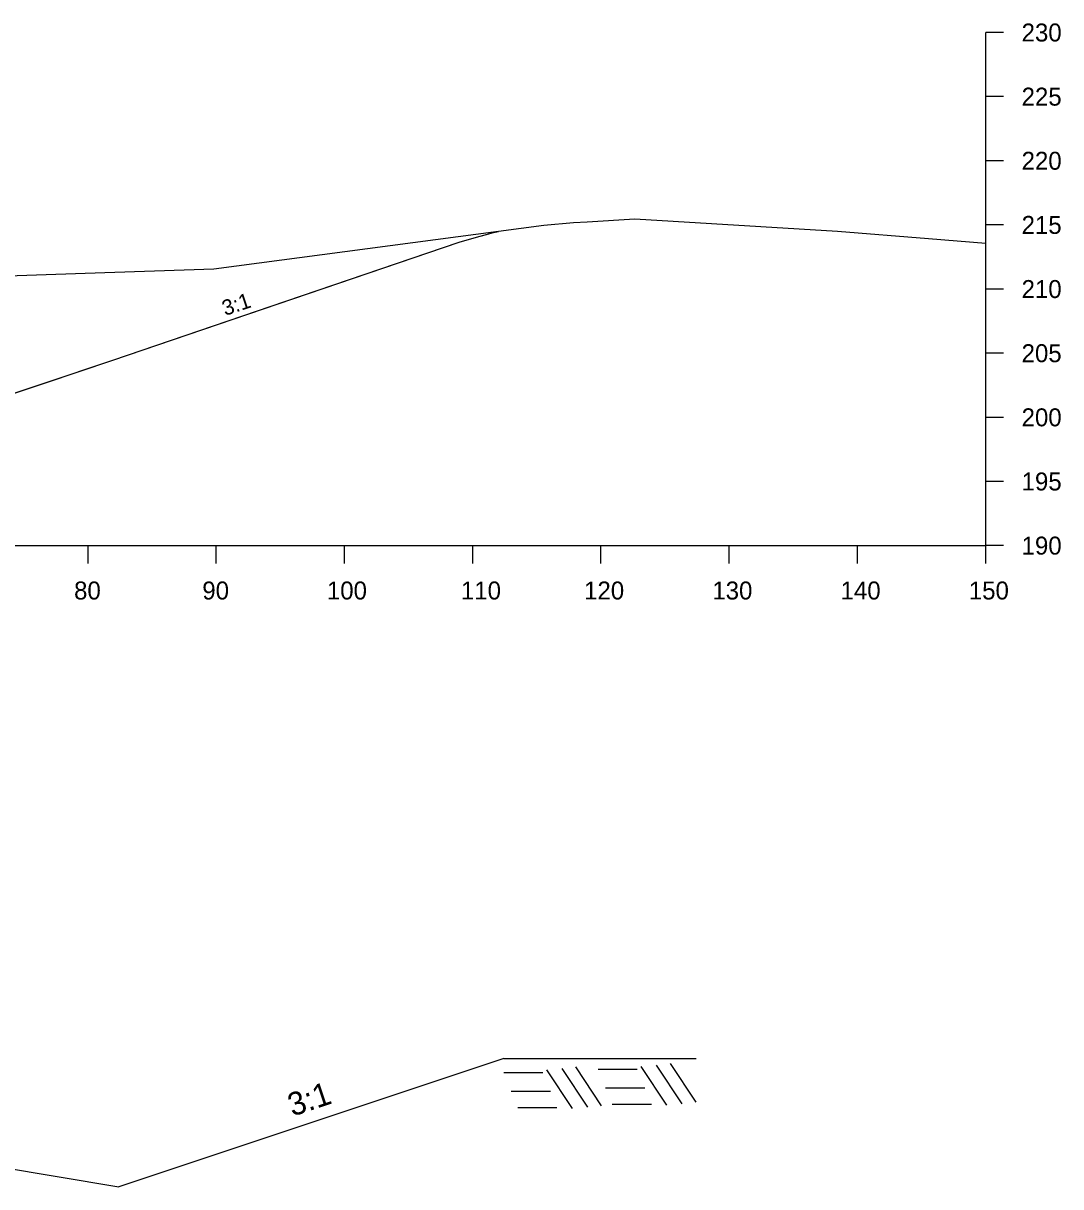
# Model space of a CAD drawing. Extents: x 2829243 to 2838161, y 467639 to 474695.
# Drawn here: x 2832546.7 to 2832951.2, y 469720.4 to 470173.9 of the extents above; entities that cross this region are included whole.
import ezdxf

# ---------------------------------------------------------------- set-up
doc = ezdxf.new("R2010")
doc.units = 0
for name, color, linetype in [('R_Axis', 7, 'Continuous'), ('R_Axis Annot', 7, 'Continuous'), ('R_Detour', 7, 'Continuous'), ('R_Draft', 7, 'Continuous'), ('R_Exist Surface', 7, 'Continuous'), ('R_Fin Surface', 7, 'Continuous'), ('R_Xsect Slope', 7, 'Continuous')]:
    doc.layers.add(name, color=color, linetype=linetype)

msp = doc.modelspace()

# ---------------------------------------------------------------- linework, layer by layer
at = {"layer": 'R_Axis'}
for p, q in [((2832921.96, 469970.29), (2832921.96, 470170.29)), ((2832928.96, 470170.29), (2832921.96, 470170.29)), ((2832928.96, 470145.29), (2832921.96, 470145.29)), ((2832928.96, 470120.29), (2832921.96, 470120.29)), ((2832928.96, 470095.29), (2832921.96, 470095.29)), ((2832928.96, 470070.29), (2832921.96, 470070.29)), ((2832928.96, 470045.29), (2832921.96, 470045.29)), ((2832928.96, 470020.29), (2832921.96, 470020.29)), ((2832928.96, 469995.29), (2832921.96, 469995.29)), ((2831421.96, 469970.29), (2832921.96, 469970.29)), ((2832571.96, 469963.29), (2832571.96, 469970.29)), ((2832621.96, 469963.29), (2832621.96, 469970.29)), ((2832671.96, 469963.29), (2832671.96, 469970.29)), ((2832721.96, 469963.29), (2832721.96, 469970.29)), ((2832771.96, 469963.29), (2832771.96, 469970.29)), ((2832821.96, 469963.29), (2832821.96, 469970.29)), ((2832871.96, 469963.29), (2832871.96, 469970.29)), ((2832921.96, 469963.29), (2832921.96, 469970.29)), ((2832928.96, 469970.29), (2832921.96, 469970.29))]:
    msp.add_line(p, q, dxfattribs=at)
at = {"layer": 'R_Detour'}
msp.add_lwpolyline([(2832268.39, 470078.52), (2832279.4, 470078.3), (2832288.39, 470078.12), (2832305.24, 470077.79), (2832325.89, 470077.37), (2832342.73, 470077.04), (2832363.39, 470076.62), (2832368.9, 470076.51), (2832373.39, 470076.42), (2832380.55, 470074.04), (2832389.35, 470071.1), (2832466.05, 470045.54), (2832528.3, 470024.79), (2832581.64, 470042.56), (2832716.63, 470088.59), (2832723.46, 470090.52), (2832731.53, 470092.77)], dxfattribs=at)
at = {"layer": 'R_Draft'}
for p, q in [((2832734.02, 469770.39), (2832584.02, 469720.39)), ((2832734.02, 469770.39), (2832809.02, 469770.39)), ((2832760.82, 469750.83), (2832750.8, 469765.93)), ((2832766.83, 469751.4), (2832756.82, 469766.51)), ((2832772.22, 469751.98), (2832762.2, 469767.09)), ((2832786.1, 469766.14), (2832770.83, 469766.14)), ((2832797.62, 469752.15), (2832787.61, 469767.26)), ((2832803.63, 469752.73), (2832793.62, 469767.83)), ((2832809.02, 469753.31), (2832799.01, 469768.42)), ((2832749.29, 469764.82), (2832734.02, 469764.82)), ((2832752.24, 469757.53), (2832736.97, 469757.53)), ((2832789.04, 469758.86), (2832773.77, 469758.86)), ((2832791.62, 469752.45), (2832776.35, 469752.45)), ((2832754.81, 469751.12), (2832739.55, 469751.12)), ((2832536.26, 469728.35), (2832584.02, 469720.39))]:
    msp.add_line(p, q, dxfattribs=at)
at = {"layer": 'R_Exist Surface'}
msp.add_lwpolyline([(2832513.84, 470074.54), (2832570.91, 470076.45), (2832621.08, 470078.12), (2832749.69, 470095.18), (2832761.21, 470096.19), (2832766.58, 470096.52), (2832785.19, 470097.7), (2832864.18, 470092.87), (2832899.67, 470090.01), (2832921.96, 470088.21)], dxfattribs=at)
at = {"layer": 'R_Fin Surface'}
msp.add_lwpolyline([(2832389.58, 470071.03), (2832528.3, 470024.79), (2832554.97, 470033.67), (2832581.64, 470042.56), (2832649.13, 470065.57), (2832716.63, 470088.59), (2832723.46, 470090.52), (2832726.78, 470091.45), (2832730.1, 470092.37), (2832731.99, 470092.68)], dxfattribs=at)

# ---------------------------------------------------------------- texts
at = {"layer": 'R_Axis Annot'}
for s, p in [('230', (2832935.96, 470166.79)), ('225', (2832935.96, 470141.79)), ('220', (2832935.96, 470116.79)), ('215', (2832935.96, 470091.79)), ('210', (2832935.96, 470066.79)), ('205', (2832935.96, 470041.79)), ('200', (2832935.96, 470016.79)), ('195', (2832935.96, 469991.79)), ('190', (2832935.96, 469966.79)), ('80', (2832566.53, 469949.29)), ('90', (2832616.53, 469949.29)), ('100', (2832665.1, 469949.29)), ('110', (2832717.36, 469949.29)), ('120', (2832765.38, 469949.29)), ('130', (2832815.38, 469949.29)), ('140', (2832865.38, 469949.29)), ('150', (2832915.38, 469949.29))]:
    msp.add_text(s, height=7, dxfattribs=at).set_placement(p)
at = {"layer": 'R_Draft'}
msp.add_text('3:1', height=9, rotation=18.4349, dxfattribs=at).set_placement((2832651.68, 469747.69))
at = {"layer": 'R_Xsect Slope'}
msp.add_text('3:1', height=6, rotation=18.4349, dxfattribs=at).set_placement((2832625.41, 470059.79))

doc.saveas('drawing.dxf')
